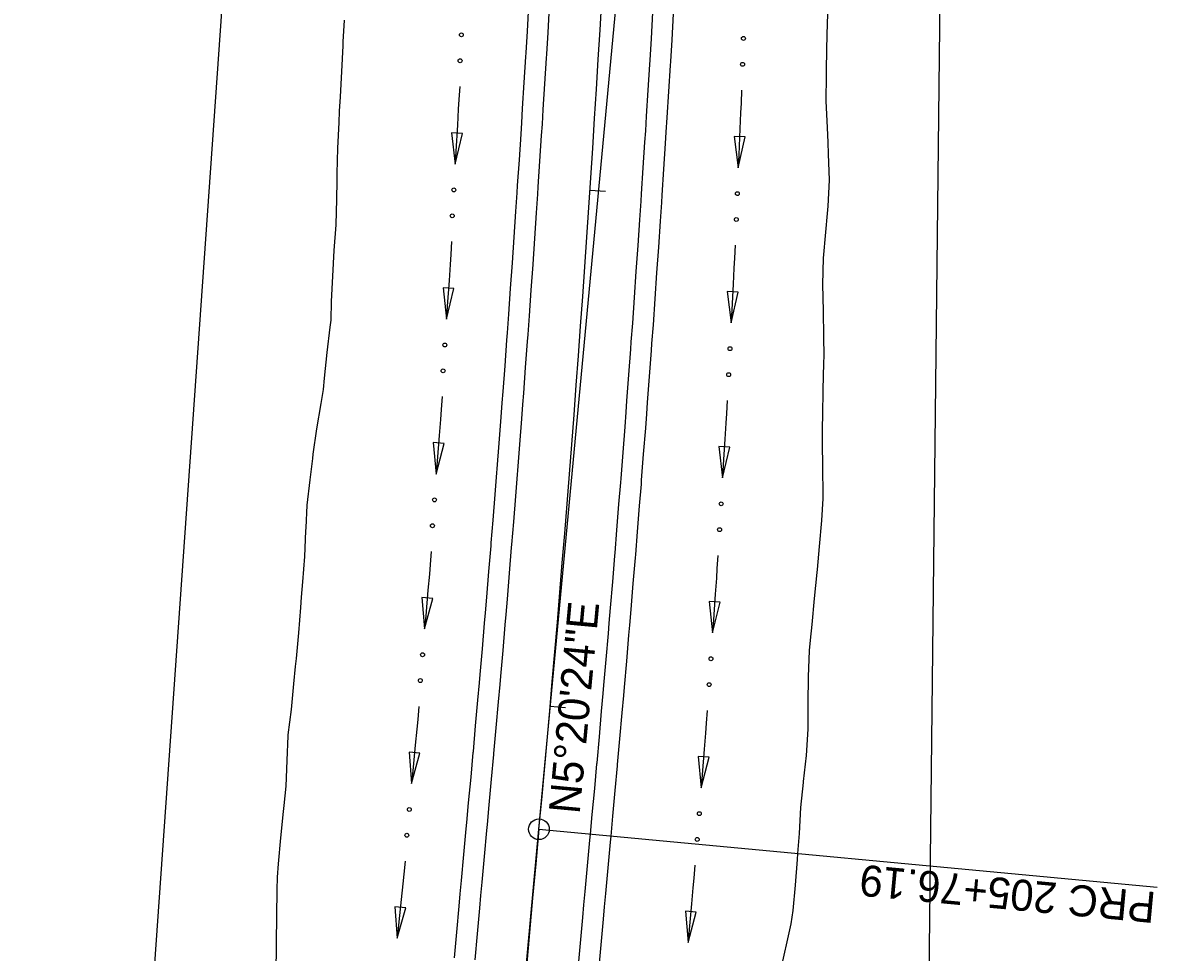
# Model space of a CAD drawing. Extents: x 1 to 1477871, y 1 to 1872901.
# Drawn here: x 1438531.3 to 1438750.6, y 1870488.2 to 1870667.7 of the extents above; entities that cross this region are included whole.
import ezdxf

# ---------------------------------------------------------------- set-up
doc = ezdxf.new("R2010")
doc.units = 0
for name, color, linetype in [('R_Horz Alg', 7, 'Continuous'), ('R_Horz Alg Annot', 7, 'Continuous'), ('R_Proposed Const Limits_Cut', 7, 'Continuous'), ('R_Proposed Road_Lane', 7, 'Continuous'), ('R_Proposed Road_Shoulder', 7, 'Continuous'), ('R_ROW', 7, 'Continuous'), ('R_Water', 7, 'Continuous')]:
    doc.layers.add(name, color=color, linetype=linetype)

msp = doc.modelspace()

# ---------------------------------------------------------------- linework, layer by layer
at = {"layer": 'R_Horz Alg'}
for centre, start, end in [((1434067.32, 1870938.5), 354.66013, 359.25), ((1443194.86, 1870085.35), 174.66013, 180)]:
    msp.add_arc(centre, 4583.66, start, end, dxfattribs=at)
at = {"layer": 'R_Horz Alg Annot'}
for p, q in [((1438631.09, 1870511.92), (1438648.18, 1870694.82)), ((1438611.19, 1870299.1), (1438631.09, 1870511.92))]:
    msp.add_line(p, q, dxfattribs=at)
for points in [[(1438643.94, 1870635.14), (1438640.94, 1870635.34)], [(1438636.23, 1870535.37), (1438633.24, 1870535.64)], [(1438631.09, 1870511.92), (1438750.57, 1870500.76)]]:
    msp.add_lwpolyline(points, dxfattribs=at)
msp.add_circle((1438631.09, 1870511.92), 2, dxfattribs=at)
at = {"layer": 'R_Proposed Const Limits_Cut'}
for points in [[(1438678.24, 1870486.46), (1438679.32, 1870491.33), (1438679.84, 1870493.68), (1438680.2, 1870496.22), (1438680.67, 1870501.14), (1438681.04, 1870506.07), (1438681.13, 1870507.25), (1438681.42, 1870511.09), (1438681.66, 1870516.14), (1438682.19, 1870520.96), (1438682.22, 1870521.17), (1438682.78, 1870526.19), (1438683.08, 1870531.24), (1438683.11, 1870534.68), (1438683.12, 1870536.31), (1438683.17, 1870541.38), (1438683.38, 1870546.43), (1438683.58, 1870548.43), (1438683.86, 1870551.46), (1438684.34, 1870556.49), (1438684.82, 1870561.53), (1438684.88, 1870562.12), (1438685.29, 1870566.56), (1438685.77, 1870571.59), (1438686.01, 1870575.82), (1438686.01, 1870576.64), (1438685.96, 1870581.71), (1438685.9, 1870586.78), (1438685.87, 1870589.61), (1438685.91, 1870591.85), (1438686.03, 1870596.91), (1438686.14, 1870601.97), (1438686.17, 1870603.37), (1438686.13, 1870607.03), (1438686.04, 1870612.1), (1438685.95, 1870617.16), (1438685.95, 1870617.17), (1438686.07, 1870622.22), (1438686.51, 1870627.26), (1438686.82, 1870630.86), (1438686.95, 1870632.29), (1438687.24, 1870637.33), (1438687.05, 1870642.4), (1438686.95, 1870644.62), (1438686.81, 1870647.48), (1438686.59, 1870652.55), (1438686.65, 1870657.6), (1438686.66, 1870658.4), (1438686.71, 1870662.66), (1438686.87, 1870667.71), (1438687.02, 1870672.13)], [(1438580.3, 1870485.02), (1438580.37, 1870488.69), (1438580.39, 1870490.08), (1438580.44, 1870495.15), (1438580.49, 1870500.22), (1438580.58, 1870502.66), (1438580.79, 1870505.27), (1438581.2, 1870510.3), (1438581.73, 1870515.33), (1438581.86, 1870516.53), (1438582.24, 1870520.28), (1438582.45, 1870525.22), (1438582.66, 1870529.96), (1438582.66, 1870530.17), (1438583.26, 1870535.08), (1438583.74, 1870540), (1438584.06, 1870543.34), (1438584.21, 1870544.93), (1438584.67, 1870549.85), (1438585.08, 1870554.78), (1438585.24, 1870556.74), (1438585.49, 1870559.71), (1438585.88, 1870564.64), (1438586.06, 1870569.59), (1438586.1, 1870570.17), (1438586.33, 1870574.53), (1438586.86, 1870579.45), (1438587.42, 1870583.56), (1438587.49, 1870584.36), (1438588.2, 1870589.26), (1438589.03, 1870594.16), (1438589.44, 1870596.9), (1438589.65, 1870599.07), (1438590.19, 1870604), (1438590.75, 1870608.92), (1438590.91, 1870610.28), (1438591, 1870613.86), (1438591.24, 1870618.8), (1438591.53, 1870623.73), (1438591.53, 1870623.74), (1438591.88, 1870628.67), (1438592.02, 1870633.62), (1438592.07, 1870637.18), (1438592.09, 1870638.58), (1438592.2, 1870643.53), (1438592.46, 1870648.47), (1438592.58, 1870650.62), (1438592.72, 1870653.41), (1438592.98, 1870658.34), (1438593.23, 1870663.29), (1438593.27, 1870664.06), (1438593.51, 1870668.22)]]:
    msp.add_lwpolyline(points, dxfattribs=at)
at = {"layer": 'R_Proposed Road_Lane'}
for points in [[(1438618.76, 1870486.72), (1438619.2, 1870491.71), (1438619.65, 1870496.7), (1438619.86, 1870499.1), (1438620.1, 1870501.69), (1438620.56, 1870506.68), (1438621.02, 1870511.67), (1438621.13, 1870512.85), (1438621.48, 1870516.64), (1438621.94, 1870521.61), (1438622.37, 1870526.37), (1438622.39, 1870526.58), (1438622.84, 1870531.55), (1438623.28, 1870536.52), (1438623.57, 1870539.88), (1438623.72, 1870541.49), (1438624.15, 1870546.46), (1438624.57, 1870551.43), (1438624.74, 1870553.4), (1438624.99, 1870556.4), (1438625.4, 1870561.37), (1438625.81, 1870566.34), (1438625.86, 1870566.93), (1438626.22, 1870571.32), (1438626.61, 1870576.29), (1438626.94, 1870580.45), (1438627.01, 1870581.26), (1438627.39, 1870586.24), (1438627.77, 1870591.21), (1438627.99, 1870593.98), (1438628.15, 1870596.19), (1438628.52, 1870601.16), (1438628.89, 1870606.14), (1438628.99, 1870607.52), (1438629.25, 1870611.11), (1438629.6, 1870616.09), (1438629.95, 1870621.05), (1438629.95, 1870621.07), (1438630.29, 1870626.04), (1438630.63, 1870631.02), (1438630.87, 1870634.59), (1438630.96, 1870636), (1438631.29, 1870640.98), (1438631.61, 1870645.96), (1438631.75, 1870648.13), (1438631.93, 1870650.94), (1438632.24, 1870655.92), (1438632.55, 1870660.89), (1438632.59, 1870661.68), (1438632.85, 1870665.87), (1438633.14, 1870670.85)], [(1438638.69, 1870484.97), (1438639.12, 1870489.94), (1438639.57, 1870494.91), (1438639.78, 1870497.3), (1438640.02, 1870499.88), (1438640.47, 1870504.84), (1438640.93, 1870509.81), (1438641.04, 1870510.99), (1438641.4, 1870514.8), (1438641.86, 1870519.79), (1438642.29, 1870524.56), (1438642.31, 1870524.78), (1438642.76, 1870529.77), (1438643.2, 1870534.76), (1438643.5, 1870538.14), (1438643.64, 1870539.75), (1438644.07, 1870544.74), (1438644.5, 1870549.74), (1438644.67, 1870551.72), (1438644.92, 1870554.73), (1438645.34, 1870559.72), (1438645.75, 1870564.72), (1438645.79, 1870565.3), (1438646.15, 1870569.71), (1438646.55, 1870574.71), (1438646.88, 1870578.89), (1438646.95, 1870579.7), (1438647.33, 1870584.7), (1438647.72, 1870589.69), (1438647.93, 1870592.48), (1438648.09, 1870594.69), (1438648.47, 1870599.69), (1438648.83, 1870604.68), (1438648.93, 1870606.07), (1438649.2, 1870609.68), (1438649.55, 1870614.68), (1438649.9, 1870619.67), (1438649.9, 1870619.68), (1438650.25, 1870624.68), (1438650.59, 1870629.68), (1438650.83, 1870633.26), (1438650.92, 1870634.68), (1438651.25, 1870639.68), (1438651.57, 1870644.68), (1438651.71, 1870646.86), (1438651.89, 1870649.68), (1438652.2, 1870654.68), (1438652.51, 1870659.68), (1438652.56, 1870660.47), (1438652.81, 1870664.68), (1438653.11, 1870669.69)]]:
    msp.add_lwpolyline(points, dxfattribs=at)
at = {"layer": 'R_Proposed Road_Shoulder'}
for points in [[(1438614.78, 1870487.06), (1438615.22, 1870492.06), (1438615.66, 1870497.06), (1438615.88, 1870499.46), (1438616.12, 1870502.05), (1438616.57, 1870507.04), (1438617.04, 1870512.04), (1438617.15, 1870513.23), (1438617.5, 1870517.01), (1438617.96, 1870521.97), (1438618.39, 1870526.73), (1438618.41, 1870526.94), (1438618.85, 1870531.9), (1438619.29, 1870536.87), (1438619.59, 1870540.23), (1438619.73, 1870541.83), (1438620.16, 1870546.8), (1438620.58, 1870551.77), (1438620.75, 1870553.74), (1438621, 1870556.73), (1438621.42, 1870561.7), (1438621.83, 1870566.67), (1438621.87, 1870567.25), (1438622.23, 1870571.64), (1438622.63, 1870576.61), (1438622.96, 1870580.77), (1438623.02, 1870581.57), (1438623.41, 1870586.54), (1438623.79, 1870591.52), (1438624, 1870594.29), (1438624.16, 1870596.49), (1438624.53, 1870601.46), (1438624.9, 1870606.43), (1438625, 1870607.81), (1438625.26, 1870611.4), (1438625.61, 1870616.37), (1438625.96, 1870621.33), (1438625.96, 1870621.34), (1438626.3, 1870626.32), (1438626.64, 1870631.29), (1438626.88, 1870634.86), (1438626.97, 1870636.26), (1438627.3, 1870641.24), (1438627.62, 1870646.21), (1438627.76, 1870648.39), (1438627.94, 1870651.19), (1438628.25, 1870656.16), (1438628.55, 1870661.14), (1438628.6, 1870661.92), (1438628.85, 1870666.11), (1438629.15, 1870671.09)], [(1438642.67, 1870484.62), (1438643.11, 1870489.58), (1438643.55, 1870494.55), (1438643.77, 1870496.94), (1438644, 1870499.51), (1438644.46, 1870504.48), (1438644.92, 1870509.44), (1438645.03, 1870510.62), (1438645.38, 1870514.43), (1438645.84, 1870519.42), (1438646.28, 1870524.21), (1438646.29, 1870524.42), (1438646.74, 1870529.41), (1438647.19, 1870534.41), (1438647.48, 1870537.79), (1438647.62, 1870539.4), (1438648.06, 1870544.4), (1438648.48, 1870549.4), (1438648.65, 1870551.38), (1438648.91, 1870554.39), (1438649.32, 1870559.39), (1438649.73, 1870564.39), (1438649.78, 1870564.98), (1438650.14, 1870569.39), (1438650.54, 1870574.39), (1438650.87, 1870578.57), (1438650.93, 1870579.39), (1438651.32, 1870584.39), (1438651.71, 1870589.39), (1438651.92, 1870592.18), (1438652.08, 1870594.39), (1438652.46, 1870599.39), (1438652.82, 1870604.39), (1438652.92, 1870605.78), (1438653.19, 1870609.4), (1438653.54, 1870614.4), (1438653.89, 1870619.39), (1438653.89, 1870619.4), (1438654.24, 1870624.4), (1438654.58, 1870629.41), (1438654.82, 1870633), (1438654.91, 1870634.41), (1438655.24, 1870639.42), (1438655.56, 1870644.42), (1438655.7, 1870646.61), (1438655.88, 1870649.43), (1438656.2, 1870654.43), (1438656.5, 1870659.44), (1438656.55, 1870660.22), (1438656.8, 1870664.44), (1438657.1, 1870669.45)]]:
    msp.add_lwpolyline(points, dxfattribs=at)
at = {"layer": 'R_ROW'}
for p, q in [((1438531.34, 1870121.98), (1438591.99, 1870985.89)), ((1438711.98, 1870984.32), (1438701.19, 1870006.35))]:
    msp.add_line(p, q, dxfattribs=at)
at = {"layer": 'R_Water'}
for p, q in [((1438616.3, 1870646.36), (1438614.19, 1870646.48)), ((1438614.19, 1870646.48), (1438614.9, 1870640.43)), ((1438614.9, 1870640.43), (1438616.3, 1870646.36)), ((1438670.92, 1870645.68), (1438668.8, 1870645.76)), ((1438668.8, 1870645.76), (1438669.61, 1870639.72)), ((1438669.61, 1870639.72), (1438670.92, 1870645.68)), ((1438614.67, 1870616.4), (1438612.56, 1870616.54)), ((1438612.56, 1870616.54), (1438613.21, 1870610.48)), ((1438613.21, 1870610.48), (1438614.67, 1870616.4)), ((1438669.59, 1870615.7), (1438667.47, 1870615.8)), ((1438667.47, 1870615.8), (1438668.22, 1870609.76)), ((1438668.22, 1870609.76), (1438669.59, 1870615.7)), ((1438612.77, 1870586.45), (1438610.66, 1870586.61)), ((1438610.66, 1870586.61), (1438611.25, 1870580.55)), ((1438611.25, 1870580.55), (1438612.77, 1870586.45)), ((1438667.97, 1870585.73), (1438665.86, 1870585.86)), ((1438665.86, 1870585.86), (1438666.56, 1870579.8)), ((1438666.56, 1870579.8), (1438667.97, 1870585.73)), ((1438610.57, 1870556.52), (1438608.46, 1870556.7)), ((1438608.46, 1870556.7), (1438609, 1870550.63)), ((1438609, 1870550.63), (1438610.57, 1870556.52)), ((1438666.1, 1870555.78), (1438663.99, 1870555.92)), ((1438663.99, 1870555.92), (1438664.63, 1870549.87)), ((1438664.63, 1870549.87), (1438666.1, 1870555.78)), ((1438608.1, 1870526.61), (1438605.99, 1870526.81)), ((1438605.99, 1870526.81), (1438606.48, 1870520.74)), ((1438606.48, 1870520.74), (1438608.1, 1870526.61)), ((1438663.95, 1870525.85), (1438661.84, 1870526.01)), ((1438661.84, 1870526.01), (1438662.43, 1870519.95)), ((1438662.43, 1870519.95), (1438663.95, 1870525.85)), ((1438605.36, 1870496.73), (1438603.25, 1870496.95)), ((1438603.25, 1870496.95), (1438603.68, 1870490.87)), ((1438603.68, 1870490.87), (1438605.36, 1870496.73)), ((1438661.49, 1870495.94), (1438659.38, 1870496.12)), ((1438659.38, 1870496.12), (1438659.92, 1870490.05)), ((1438659.92, 1870490.05), (1438661.49, 1870495.94))]:
    msp.add_line(p, q, dxfattribs=at)
for points in [[(1438615.77, 1870655.41), (1438615.62, 1870652.89), (1438615.51, 1870651.01), (1438615.33, 1870647.92), (1438615.04, 1870642.94), (1438614.9, 1870640.43)], [(1438670.23, 1870654.71), (1438670.13, 1870652.2), (1438670.05, 1870650.31), (1438669.92, 1870647.22), (1438669.72, 1870642.24), (1438669.61, 1870639.72)], [(1438614.22, 1870625.45), (1438614.05, 1870622.93), (1438613.92, 1870621.05), (1438613.71, 1870617.96), (1438613.38, 1870612.99), (1438613.21, 1870610.48)], [(1438668.98, 1870624.74), (1438668.86, 1870622.22), (1438668.76, 1870620.34), (1438668.61, 1870617.25), (1438668.35, 1870612.27), (1438668.22, 1870609.76)], [(1438612.4, 1870595.5), (1438612.21, 1870592.99), (1438612.07, 1870591.11), (1438611.83, 1870588.02), (1438611.44, 1870583.05), (1438611.25, 1870580.55)], [(1438667.45, 1870594.78), (1438667.3, 1870592.26), (1438667.19, 1870590.38), (1438667, 1870587.29), (1438666.71, 1870582.31), (1438666.56, 1870579.8)], [(1438610.28, 1870565.58), (1438610.07, 1870563.07), (1438609.91, 1870561.19), (1438609.64, 1870558.1), (1438609.21, 1870553.14), (1438609, 1870550.63)], [(1438665.67, 1870564.83), (1438665.49, 1870562.32), (1438665.37, 1870560.44), (1438665.15, 1870557.35), (1438664.81, 1870552.37), (1438664.63, 1870549.87)], [(1438607.9, 1870535.67), (1438607.66, 1870533.16), (1438607.48, 1870531.29), (1438607.19, 1870528.2), (1438606.72, 1870523.24), (1438606.48, 1870520.74)], [(1438663.6, 1870534.9), (1438663.4, 1870532.39), (1438663.26, 1870530.51), (1438663.02, 1870527.42), (1438662.63, 1870522.45), (1438662.43, 1870519.95)], [(1438605.23, 1870505.79), (1438604.98, 1870503.28), (1438604.78, 1870501.41), (1438604.46, 1870498.33), (1438603.94, 1870493.37), (1438603.68, 1870490.87)], [(1438661.21, 1870505), (1438660.99, 1870502.49), (1438660.83, 1870500.61), (1438660.56, 1870497.52), (1438660.14, 1870492.56), (1438659.92, 1870490.05)]]:
    msp.add_lwpolyline(points, dxfattribs=at)
for centre in [(1438616.1, 1870665.39), (1438670.6, 1870664.7), (1438615.85, 1870660.39), (1438670.43, 1870659.69), (1438614.64, 1870635.43), (1438669.43, 1870634.72), (1438614.34, 1870630.43), (1438669.22, 1870629.72), (1438612.9, 1870605.48), (1438668, 1870604.76), (1438612.56, 1870600.48), (1438667.74, 1870599.75), (1438610.9, 1870575.55), (1438666.29, 1870574.8), (1438610.51, 1870570.56), (1438665.99, 1870569.8), (1438608.6, 1870545.64), (1438664.32, 1870544.87), (1438608.17, 1870540.65), (1438663.97, 1870539.87), (1438606.04, 1870515.75), (1438662.07, 1870514.95), (1438605.56, 1870510.77), (1438661.67, 1870509.96)]:
    msp.add_circle(centre, 0.375, dxfattribs=at)

# ---------------------------------------------------------------- texts
at = {"layer": 'R_Horz Alg Annot'}
for s, rotation, p in [('N5%%d20\'24"E', 84.6601, (1438638.94, 1870514.74)), ('PRC 205+76.19', 174.6601, (1438750.47, 1870499.76))]:
    msp.add_text(s, height=6, rotation=rotation, dxfattribs=at).set_placement(p)

doc.saveas('drawing.dxf')
